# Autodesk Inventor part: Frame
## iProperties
Created: 2007-12
Part Number: Frame
Document SubType Name: Modeling
Designer: UJA2299
Material: Aluminum-6061
Mass: 18.8443 g
Surface Area: 45.8273 cm^2
Volume: 6.9536 cm^3
Density: 2.71 g/cm^3
Author: UJA2299
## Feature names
1. 押し出し1 [Extrusion]
2. 分割1
3. 押し出し2 [Extrusion]
4. 押し出し3 [Extrusion]
5. 押し出し4 [Extrusion]
6. 押し出し5 [Extrusion]
7. 押し出し6 [Extrusion]
8. 押し出し7 [Extrusion]
9. 押し出し8 [Extrusion]
10. 押し出し9 [Extrusion]
11. 押し出し10 [Extrusion]
12. 押し出し11 [Extrusion]
13. 押し出し12 [Extrusion]
14. 面取り1 [Chamfer]
15. 面取り2 [Chamfer]
16. 押し出し14 [Extrusion]
17. 押し出し15 [Extrusion]
18. 押し出し16 [Extrusion]
19. 押し出し17 [Extrusion]
20. フィレット1 [Fillet]
21. フィレット3 [Fillet]
22. フィレット4 [Fillet]
23. 押し出し18 [Extrusion]
24. フィレット5 [Fillet]
25. フィレット6 [Fillet]
26. フィレット7 [Fillet]
27. フィレット8 [Fillet]
28. フィレット9 [Fillet]
29. フィレット10 [Fillet]
30. フィレット11 [Fillet]
